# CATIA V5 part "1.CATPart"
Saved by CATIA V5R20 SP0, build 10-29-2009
Part number: Part1
Material "Steel": density 7860 kg/m3, Young's modulus 2e+11 Pa, Poisson ratio 0.266, thermal expansion 1.17e-05 1/K
Bounding box of the stored display mesh (mm): x -425 to 425, y -257.5 to 257.5, z -207 to 1
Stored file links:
  E:\Ehsan\Amoozesh\CATIA\CATIA Course\Advanced\Videos\Session-17\1.CATPart
  D:\CATIA V5R20\B20\intel_a\startup\materials\Catalog.CATMaterial
  D:\CATIA V5R20\B20\intel_a\resources\graphic\figures\CATIA_EnvironmentMap_Satin_512x512.jpg
  D:\CATIA V5R20\B20\intel_a\resources\graphic\figures\CATIA_EnvironmentMap_DSRed_512x512.jpg
  D:\CATIA V5R20\B20\intel_a\resources\graphic\figures\CATIA_EnvironmentMap_Field_512x512.jpg
  D:\CATIA V5R20\B20\intel_a\resources\graphic\figures\CATIA_EnvironmentMap_Default_512x512.jpg
  D:\CATIA V5R20\B20\intel_a\resources\graphic\figures\CATIA_EnvironmentMap_DSBrown_512x512.jpg
  D:\CATIA V5R20\B20\intel_a\resources\graphic\figures\CATIA_EnvironmentMap_DSBlack_512x512.jpg
  D:\CATIA V5R20\B20\intel_a\resources\graphic\figures\CATIA_EnvironmentMap_DSGreen_512x512.jpg
  D:\CATIA V5R20\B20\intel_a\resources\graphic\figures\CATIA_EnvironmentMap_DSYellow_512x512.jpg
  D:\CATIA V5R20\B20\intel_a\resources\graphic\figures\CATIA_EnvironmentMap_Neons1_512x512.jpg
  D:\CATIA V5R20\B20\intel_a\resources\graphic\figures\CATIA_EnvironmentMap_GridSpot_512x512.jpg
  D:\CATIA V5R20\B20\intel_a\resources\graphic\figures\CATIA_EnvironmentMap_Neons2_512x512.jpg
  D:\CATIA V5R20\B20\intel_a\resources\graphic\figures\CATIA_EnvironmentMap_NumberRoom_512x512.jpg
  D:\CATIA V5R20\B20\intel_a\resources\graphic\figures\CATIA_EnvironmentMap_YellowSatin_512x512.jpg
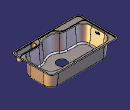
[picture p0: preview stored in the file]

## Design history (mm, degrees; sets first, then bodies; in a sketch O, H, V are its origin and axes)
SheetMetalParameters1: Thickness 1, BendRadius 1, KFactor 0.325257 {= log(min(100,max(20*SheetMetalParameters1.BendRadius,SheetMetalParameters1.Thickness)/SheetMetalParameters1.Thickness))/log(100)/2}, ReliefRadialLength 1, ReliefAxialLength 2, MinimumBendRadius 0
AxisSystem1: origin (0, 0, 0), X (1, 0, 0), Y (0, 1, 0), Z (0, 0, 1)
Body1 (main body), material "Steel"
  Sketch1 on XY plane of AxisSystem1, origin (0, 0, 0), H (-1, 0, 0), V (0, -1, 0)
    line L1 (425, 207.5) -> (425, -207.5)
    line L2 (375, -257.5) -> (-375, -257.5)
    line L3 (-425, -207.5) -> (-425, 207.5)
    line L4 (-375, 257.5) -> (375, 257.5)
    arc A1 centre (375, 207.5) radius 50 from (425, 207.5) to (375, 257.5) ccw
    arc A2 centre (375, -207.5) radius 50 from (425, -207.5) to (375, -257.5) cw
    arc A3 centre (-375, -207.5) radius 50 from (-375, -257.5) to (-425, -207.5) cw
    arc A4 centre (-375, 207.5) radius 50 from (-425, 207.5) to (-375, 257.5) cw
    distance L2 L4 = 515
    distance L1 L3 = 850
    radius A1 = 50
    radius A2 = 50 {= Sketch1.radius(A1)}
    radius A3 = 50 {= Sketch1.radius(A1)}
    radius A4 = 50 {= Sketch1.radius(A1)}
    vertical: L1 V, L3 V
    horizontal: L2 H, L4 H
    equidistance: L1 L3 O, L2 L4 O
    tangency: A1 L1, A1 L4, A2 L1, A2 L2, A3 L2, A3 L3, A4 L3, A4 L4
  Wall1: Thickness 1, Profile Sketch1
  d_Stamp1: NewRoot_AttribNormalisation "No Standard", Stamp_FilletRadius 2, Stamp_IntersectFilletRadius 2
  d_Stamp2: NewRoot_AttribNormalisation "No Standard", Stamp_FilletRadius 1, Stamp_IntersectFilletRadius 2
  d_Stamp3: NewRoot_AttribNormalisation "No Standard", Stamp_FilletRadius 5, Stamp_IntersectFilletRadius 2
  d_Stamp4: NewRoot_AttribNormalisation "No Standard", Stamp_FilletRadius 3, Stamp_IntersectFilletRadius 2
  CutOut1: Direction Sketch5, EndLimit through (limit type 3), Orientation true, Profile Sketch5, StartLimit through (limit type 2)
  CutOut2: Direction Sketch4, EndLimit through (limit type 3), Orientation true, Profile Sketch4, StartLimit through (limit type 2)
  SHM_CircPattern1: RadialStep 20, Direction face of CutOut1, Item CutOut2, RadialNumber 1, AngularNumber 6, AngularPosition 1, RadialPosition 1, AngleXY 0, AngularStep 60 {= 360.0*1 deg/SHM_CircPattern1.AngularNumber}
  CutOut3: Direction Sketch3, EndLimit length 500, Orientation true, Profile Sketch3, StartLimit length 0.01
  Sketch2 on face of d_Stamp3, origin (-58.5832, -78.1568, -206), H (1, 0, 0), V (0, 1, 0)
    point P1 (58.5831, 38.158)
    reference projected arc E1 centre (58.5831, 38.158) radius 143.7583 from (-29.3868, -75.5422) to (146.5531, -75.5422) ccw from edge [face of d_Stamp3 | face of d_Stamp3]
    concentricity: P1 E1
  Hole1: placed by Sketch2, at (0, -39.9988, -206) direction (0, 0, -1), diameter 118, depth 10
  Sketch3 on YZ plane of AxisSystem1, origin (0, 0, 0), H (0, 1, 0), V (0, 0, 1)
    circle A1 centre (25, -45) radius 2.5
    point P1 (25, -45)
    reference projected line E1 (107.5, -192.3945) -> (107.5, -11.5642) from edge [face of d_Stamp3 | face of d_Stamp3]
    reference projected line E2 (-57.5, -192.3945) -> (-57.5, -11.5642) from edge [face of d_Stamp3 | face of d_Stamp3]
    construction line L1 (17, -35) -> (17, -55)
    point P2 (17, -35)
    point P3 (17, -55)
    line L2 (20, -35) -> (20, -55)
    line L3 (14, -55) -> (14, -35)
    arc A2 centre (17, -55) radius 3 from (20, -55) to (14, -55) cw
    arc A3 centre (17, -35) radius 3 from (14, -35) to (20, -35) cw
    point P4 (20, -35)
    point P5 (20, -55)
    point P6 (14, -55)
    point P7 (14, -35)
    construction line L4 (9, -21.3824) -> (9, -65.5245)
    point P10 (4, -35)
    point P11 (4, -55)
    point P12 (-2, -55)
    point P13 (-2, -35)
    arc A4 centre (1, -35) radius 3 from (4, -35) to (-2, -35) ccw
    arc A5 centre (1, -55) radius 3 from (-2, -55) to (4, -55) ccw
    line L5 (4, -55) -> (4, -35)
    line L6 (-2, -35) -> (-2, -55)
    axis line L7 (25, -45) -> (25, -29.2463)
    point P17 (52, -35)
    point P18 (52, -55)
    point P19 (46, -55)
    point P20 (46, -35)
    line L8 (52, -35) -> (52, -55)
    line L9 (46, -55) -> (46, -35)
    arc A6 centre (49, -55) radius 3 from (52, -55) to (46, -55) cw
    arc A7 centre (49, -35) radius 3 from (46, -35) to (52, -35) cw
    point P23 (36, -35)
    point P24 (36, -55)
    point P25 (30, -55)
    point P26 (30, -35)
    arc A8 centre (33, -35) radius 3 from (36, -35) to (30, -35) ccw
    arc A9 centre (33, -55) radius 3 from (30, -55) to (36, -55) ccw
    line L10 (36, -55) -> (36, -35)
    line L11 (30, -35) -> (30, -55)
    distance L1 L2 = 3
    distance P1 H = 45
    radius A1 = 2.5
    length L3 = 20
    distance L1 P1 = 8
    distance L4 L1 = 8
    equidistance: E1 E2 P1, P2 P3 P1
    vertical: L1 V, L4 V, L7 V
    tangency: A2 L2, A3 L2, A2 L3, A3 L3
    symmetry: P7 P10 L4, P6 P11 L4, P5 P12 L4, P4 P13 L4, A3 A4 L4, A2 A5 L4, L3 L5 L4, L2 L6 L4, P13 P17 L7, P12 P18 L7, P11 P19 L7, P10 P20 L7, L6 L8 L7, L5 L9 L7, A5 A6 L7, A4 A7 L7, P7 P23 L7, P6 P24 L7, P5 P25 L7, P4 P26 L7, A3 A8 L7, A2 A9 L7, L3 L10 L7, L2 L11 L7
  Sketch4 on face of d_Stamp4, origin (0, 0, -86), H (-1, 0, 0), V (0, -1, 0)
    circle A1 centre (-275, 216.7265) radius 3.5
    axis line L1 (-275, 216.7265) -> (-275, 206.7265)
    point P2 (-275, 206.7265)
    reference projected circle E1 centre (-275, 206.7265) radius 2.5 from edge [face of CutOut1 | face of d_Stamp4]
    radius A1 = 3.5
    length L1 = 10
    vertical: L1 V
    concentricity: P2 E1
  Sketch5 on face of d_Stamp2, origin (0, 0, -6), H (-1, 0, 0), V (0, -1, 0)
    circle A1 centre (-85, 222.5) radius 2.5
    point P1 (-85, 222.5)
    reference projected line E1 (-375, 257.5) -> (375, 257.5) from edge [face of Wall1 | face of Wall1]
    circle A2 centre (-275, 206.7265) radius 2.5
    point P2 (-275, 206.7265)
    reference projected line E2 (-360, 181.7265) -> (-190, 181.7265) from Sketch6.L3
    reference projected line E3 (-190, 231.7265) -> (-360, 231.7265) from Sketch6.L2
    axis line L1 (-275, 206.7265) -> (-275, 260.5642)
    reference projected arc E4 centre (-190, 206.7265) radius 25 from (-190, 181.7265) to (-190, 231.7265) ccw from Sketch6.A1
    reference projected arc E5 centre (-360, 206.7265) radius 25 from (-360, 231.7265) to (-360, 181.7265) ccw from Sketch6.A2
    circle A3 centre (85, 222.5) radius 2.5
    distance P1 V = 85
    distance P1 E1 = 35
    radius A1 = 2.5
    radius A2 = 2.5
    equidistance: E2 E3 P2
    vertical: L1 V
    symmetry: E4 E5 L1, A1 A3 V
  Sketch6 on face of d_Stamp1, origin (0, 0, -1), H (-1, 0, 0), V (0, -1, 0)
    construction line L1 (-360, 206.7265) -> (-190, 206.7265)
    point P1 (-360, 206.7265)
    line L2 (-360, 231.7265) -> (-190, 231.7265)
    line L3 (-190, 181.7265) -> (-360, 181.7265)
    arc A1 centre (-190, 206.7265) radius 25 from (-190, 231.7265) to (-190, 181.7265) cw
    arc A2 centre (-360, 206.7265) radius 25 from (-360, 181.7265) to (-360, 231.7265) cw
    reference projected line E1 (-425, -207.5) -> (-425, 207.5) from edge [face of Wall1 | face of Wall1]
    distance L1 L2 = 25
    distance P1 E1 = 65
    length L1 = 170
    horizontal: L1 H
    tangency: A1 L2, A2 L2, A1 L3, A2 L3
  Sketch7 on face of d_Stamp2, origin (0, 0, -6), H (-1, 0, 0), V (0, -1, 0)
    point P1 (0, -25)
    line L1 (385, 57.5) -> (385, -107.5)
    line L2 (285, -207.5) -> (-285, -207.5)
    line L3 (-385, -107.5) -> (-385, 57.5)
    line L4 (-285, 157.5) -> (-168.2818, 157.5)
    reference projected line E1 (425, 207.5) -> (425, -207.5) from edge [face of Wall1 | face of Wall1]
    reference projected line E2 (375, -257.5) -> (-375, -257.5) from edge [face of Wall1 | face of Wall1]
    reference projected line E3 (-375, 257.5) -> (375, 257.5) from edge [face of Wall1 | face of Wall1]
    arc A1 centre (0, 40) radius 175 from (107.0884, 178.4091) to (-107.0884, 178.4091) ccw
    point P2 (0, 40)
    point P3 (129.6871, 157.5)
    line L5 (168.2818, 157.5) -> (285, 157.5)
    arc A2 centre (285, 57.5) radius 100 from (385, 57.5) to (285, 157.5) ccw
    arc A3 centre (285, -107.5) radius 100 from (385, -107.5) to (285, -207.5) cw
    arc A4 centre (-285, -107.5) radius 100 from (-285, -207.5) to (-385, -107.5) cw
    arc A5 centre (-285, 57.5) radius 100 from (-385, 57.5) to (-285, 157.5) cw
    arc A6 centre (-168.2818, 257.5) radius 100 from (-107.0884, 178.4091) to (-168.2818, 157.5) cw
    arc A7 centre (168.2818, 257.5) radius 100 from (107.0884, 178.4091) to (168.2818, 157.5) ccw
    distance L1 E1 = 40
    distance L2 E2 = 50
    distance L4 E3 = 100
    distance P2 V = 0
    distance P2 H = 40
    radius A1 = 175
    radius A2 = 100
    radius A3 = 100 {= Sketch7.radius(A2)}
    radius A4 = 100 {= Sketch7.radius(A2)}
    radius A5 = 100 {= Sketch7.radius(A2)}
    radius A6 = 100 {= Sketch7.radius(A2)}
    radius A7 = 100 {= Sketch7.radius(A2)}
    coincidence: P1 V, L4 P3, L4 L5, A1 P3, L5 P3
    vertical: L1 V, L3 V
    horizontal: L2 H, L4 H, L5 H
    equidistance: L1 L3 P1, L2 L4 P1
    tangency: A2 L1, A2 L5, A3 L1, A3 L2, A4 L2, A4 L3, A5 L3, A5 L4, A6 A1, A6 L4, A7 A1, A7 L5
  Sketch8 on face of d_Stamp1, origin (0, 0, -1), H (-1, 0, 0), V (0, -1, 0)
    reference projected curve E1 from face of d_Stamp1
    line L1 (-377.1716, 167.5) -> (-180, 167.5)
    point P1 (-180, 167.5)
    arc A1 centre (-180, 247.5) radius 80 from (-180, 167.5) to (-104.8793, 219.9884) ccw
    point P3 (-100.3839, 239.6716)
    point P4 (-122.8008, -239.6716)
    line L2 (-119.914, -234.6716) -> (-112.8868, -222.5)
    point P5 (-110, -217.5)
    point P6 (122.8008, -239.6716)
    line L3 (119.914, -234.6716) -> (112.8868, -222.5)
    line L4 (-104.2265, -217.5) -> (104.2265, -217.5)
    reference projected line E3 (-375, 257.5) -> (375, 257.5) from edge [face of Wall1 | face of Wall1]
    point P7 (110, -217.5)
    point P8 (-122.8008, -239.6716)
    point P9 (-407.1716, 167.5)
    point P10 (180, 167.5)
    point P11 (407.1716, 167.5)
    line L5 (377.1716, 167.5) -> (180, 167.5)
    point P12 (100.3839, 239.6716)
    arc A2 centre (180, 247.5) radius 80 from (180, 167.5) to (104.8793, 219.9884) cw
    reference projected line E4 (375, -257.5) -> (-375, -257.5) from edge [face of Wall1 | face of Wall1]
    point P14 (407.1716, 167.5)
    point P15 (122.8008, -239.6716)
    construction line L6 (-407.1716, 207.5) -> (-407.1716, -207.5001)
    construction arc A3 centre (-374.9998, -207.4998) radius 32.1718 from (-375.0001, -239.6716) to (-407.1716, -207.5001) cw
    construction line L7 (-375.0001, -239.6716) -> (375, -239.6716)
    construction arc A4 centre (374.9999, -207.4999) radius 32.1717 from (407.1716, -207.5) to (375, -239.6716) cw
    construction line L8 (407.1716, -207.5) -> (407.1716, 207.5)
    construction arc A5 centre (374.9999, 207.4999) radius 32.1717 from (375, 239.6716) to (407.1716, 207.5) cw
    construction line L9 (375, 239.6716) -> (-375, 239.6716)
    construction arc A6 centre (-374.9999, 207.4999) radius 32.1717 from (-407.1716, 207.5) to (-375, 239.6716) cw
    line L10 (128.5743, -239.6716) -> (375, -239.6716)
    arc A7 centre (374.9999, -207.4999) radius 32.1717 from (407.1716, -207.5) to (375, -239.6716) cw
    line L11 (407.1716, -207.5) -> (407.1716, 137.5)
    line L12 (-76.7091, 239.6716) -> (76.7091, 239.6716)
    arc A8 centre (-128.5743, -229.6716) radius 10 from (-119.914, -234.6716) to (-128.5743, -239.6716) cw
    arc A9 centre (-104.2265, -227.5) radius 10 from (-112.8868, -222.5) to (-104.2265, -217.5) cw
    arc A10 centre (128.5743, -229.6716) radius 10 from (119.914, -234.6716) to (128.5743, -239.6716) ccw
    arc A11 centre (104.2265, -227.5) radius 10 from (112.8868, -222.5) to (104.2265, -217.5) ccw
    arc A12 centre (-76.7091, 209.6716) radius 30 from (-104.8793, 219.9884) to (-76.7091, 239.6716) cw
    arc A13 centre (-377.1716, 137.5) radius 30 from (-407.1716, 137.5) to (-377.1716, 167.5) cw
    arc A14 centre (377.1716, 137.5) radius 30 from (377.1716, 167.5) to (407.1716, 137.5) cw
    arc A15 centre (76.7091, 209.6716) radius 30 from (104.8793, 219.9884) to (76.7091, 239.6716) ccw
    distance L1 E3 = 90
    radius A1 = 80
    distance P1 V = 180
    angle L4 L3 = 60
    distance L4 E4 = 40
    radius A8 = 10
    distance P5 P7 = 220
    radius A9 = 10 {= Sketch8.radius(A8)}
    radius A10 = 10 {= Sketch8.radius(A8)}
    radius A11 = 10 {= Sketch8.radius(A8)}
    radius A12 = 30
    radius A13 = 30 {= Sketch8.radius(A12)}
    radius A14 = 30 {= Sketch8.radius(A12)}
    radius A15 = 30 {= Sketch8.radius(A12)}
    horizontal: L1 H, L4 H
    coincidence: P3 E1, P4 E1, P4 L2, L2 P8, E1 P8, L2 P5, L4 P5, L3 P6, L10 P15, L3 P7, L4 P7, A1 P3, L12 P3, E1 P9, L1 P9, L5 P11, L11 P14, A2 P12, L12 P12
    tangency: A1 L1, L12 A5, A8 L2, A8 E1, A9 L2, A9 L4, A10 L3, A10 L10, A11 L3, A11 L4, A12 A1, A12 L12, A13 E1, A13 L1, A14 L5, A14 L11, A15 A2, A15 L12
    symmetry: P4 P6 V, L2 L3 V, P1 P10 V, P9 P11 V, L1 L5 V, P3 P12 V, A1 A2 V, P9 P14 V, P8 P15 V
  Sketch9 on face of Wall1, origin (0, 0, 1), H (-1, 0, 0), V (0, -1, 0)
